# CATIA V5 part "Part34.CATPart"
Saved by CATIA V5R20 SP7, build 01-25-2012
Part number: tige vérin droit
Publications: "Plan.1", "Corps principal", "Arête"
Bounding box of the stored display mesh (mm): x -12.584 to 14.61, y -32.162 to 26.15, z -10.979 to -2.571
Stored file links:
  F:\Travaux\Modélisations\CFAO_2011\CFAO_2011_MMS\CFAO_2011_MMS_DONE\CFAO_2011_MMS_jboiteux\Catia\Part34.CATPart
  U:\finthinkmotion\stepper.CATProduct
  F:\Travaux\Modélisations\CFAO_2011\CFAO_2011_MMS\CFAO_2011_MMS_DONE\CFAO_2011_MMS_jboiteux\Catia\bati.CATPart
  F:\Travaux\Modélisations\CFAO_2011\CFAO_2011_MMS\CFAO_2011_MMS_DONE\CFAO_2011_MMS_jboiteux\Catia\part3.CATPart
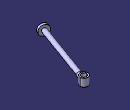
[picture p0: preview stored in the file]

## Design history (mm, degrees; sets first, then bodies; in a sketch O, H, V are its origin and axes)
Parameters
  rayontube = 9 mm {= External.royontubebati}
  longueurpied = 108 mm {= External.longueurpied}
External parameters (linked from other documents)
  External.royontubebati = 9 mm
  External.longueurpied = 108 mm
Set1
  Plane1: linked copy from another document
  Point1: linked copy from another document
  Plane2: linked copy from another document
  DatumCurve1: linked copy from another document
  Line1: linked copy from another document
Body1 (main body)
  Plane3: type OffsetPt, RefPlane Plane1, RefPoint Point1
  Sketch1 on Plane3, origin (0, 0, -5.7209), H (1, 0, 0), V (0, -1, 0)
    circle A1 centre (11.46, -23) radius 3.15
    circle A2 centre (11.46, -23) radius 2.15
    reference projected point E1 (11.46, -23) from Point1
    radius A1 = 3.15 {= rayontube *0.7/2}
    radius A2 = 2.15 {= rayontube *0.7/2-1mm}
    concentricity: E1 A2
  Pad1: profile Sketch1, direction (0, 0, 1), length 3.15 {= rayontube *0.7/2}, mirrored extent
  Sketch2 on Plane2, origin (32.9049, -0.8257, -19.4819), H (0.9094, -0.3384, -0.2418), V (0.2184, -0.1063, 0.9701)
    projected circle E1 centre (-30.8919, 6.1319) radius 1.8 from edge of DatumCurve1
  Pad2: profile Sketch2, direction (0.354, 0.935, 0.0228), length 0, opposite side length 40.5 {= longueurpied *3/8}
  Sketch3 on start face of Pad2, origin (14.7094, -37.2093, -21.2998), H (0.9094, -0.3384, -0.2418), V (0.2184, -0.1063, 0.9701)
    circle A1 centre (-27.0957, 7.9997) radius 3.95
    point P1 (-27.0957, 7.9997)
    reference projected point E1 (-27.0957, 7.9997) from Line1
    distance P1 E1 = 0
    radius A1 = 3.95 {= rayontube *1.1/2-1mm}
  Pad3: profile Sketch3, direction (-0.354, -0.935, -0.0228), length 2
  Plane4: type OffsetPt, RefPlane Plane2, RefPoint Point1
  Sketch4 on Plane2, origin (32.9049, -0.8257, -19.4819), H (0.7839, -0.3099, 0.538), V (-0.51, 0.1725, 0.8427)
    projected circle E1 centre (-16.7925, 26.6444) radius 1.8 from edge [end face of Pad2 | face of Pad2 from Sketch2.E1]
  Pad4: profile Sketch4, direction (-0.354, -0.935, -0.0228), up to Plane4, offset -6 {= -rayontube /1.5}
  Sketch5 on end face of Pad4, origin (36.5277, 7.4168, -18.9944), H (-0.9094, 0.3384, 0.2418), V (0.2184, -0.1063, 0.9701)
    circle A1 centre (31.2796, 5.7445) radius 2
    point P1 (31.2796, 5.7445)
    reference projected point E1 (31.2796, 5.7445) from Line1
    radius A1 = 2 {= rayontube *20/90}
    coincidence: E1 P1
  Pad5: profile Sketch5, direction (0.354, 0.935, 0.0228), up to face of Pad1 from Sketch1.A1
Relations
  Pad2.SecondLimit.Length = rayontube rayontube *4.5 (deactivated)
